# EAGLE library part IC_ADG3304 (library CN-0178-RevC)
Low Voltage 1.15 V to 5.5 V, 4 Channel, Bidirectional, Logic Level Translator
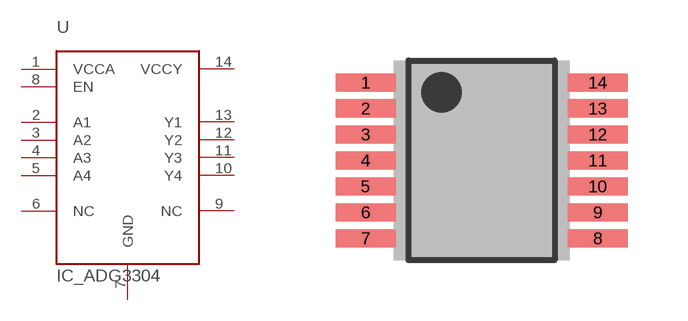
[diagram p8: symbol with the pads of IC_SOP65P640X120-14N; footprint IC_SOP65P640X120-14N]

Designator prefix U

## IC_ADG3304_TSSOP14  [IC_SOP65P640X120-14N]
1  VCCA  pas
2  A1  pas
3  A2  pas
4  A3  pas
5  A4  pas
6  NC  pas
7  GND  pas
8  EN  pas
9  NC  pas
10  Y4  pas
11  Y3  pas
12  Y2  pas
13  Y1  pas
14  VCCY  pas

## Footprint IC_SOP65P640X120-14N (pad centres in mm)
(TSSOP-14) 0.65mm pitch; 4.40mm W X 5.00mm L X 1.20mm H body; JEDEC MO-153AB-1
smd 1.5 x 0.45: 1 -2.9,1.95; 2 -2.9,1.3; 3 -2.9,0.65; 4 -2.9,0; 5 -2.9,-0.65; 6 -2.9,-1.3; 7 -2.9,-1.95; 8 2.9,-1.95; 9 2.9,-1.3; 10 2.9,-0.65; 11 2.9,0; 12 2.9,0.65; 13 2.9,1.3; 14 2.9,1.95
